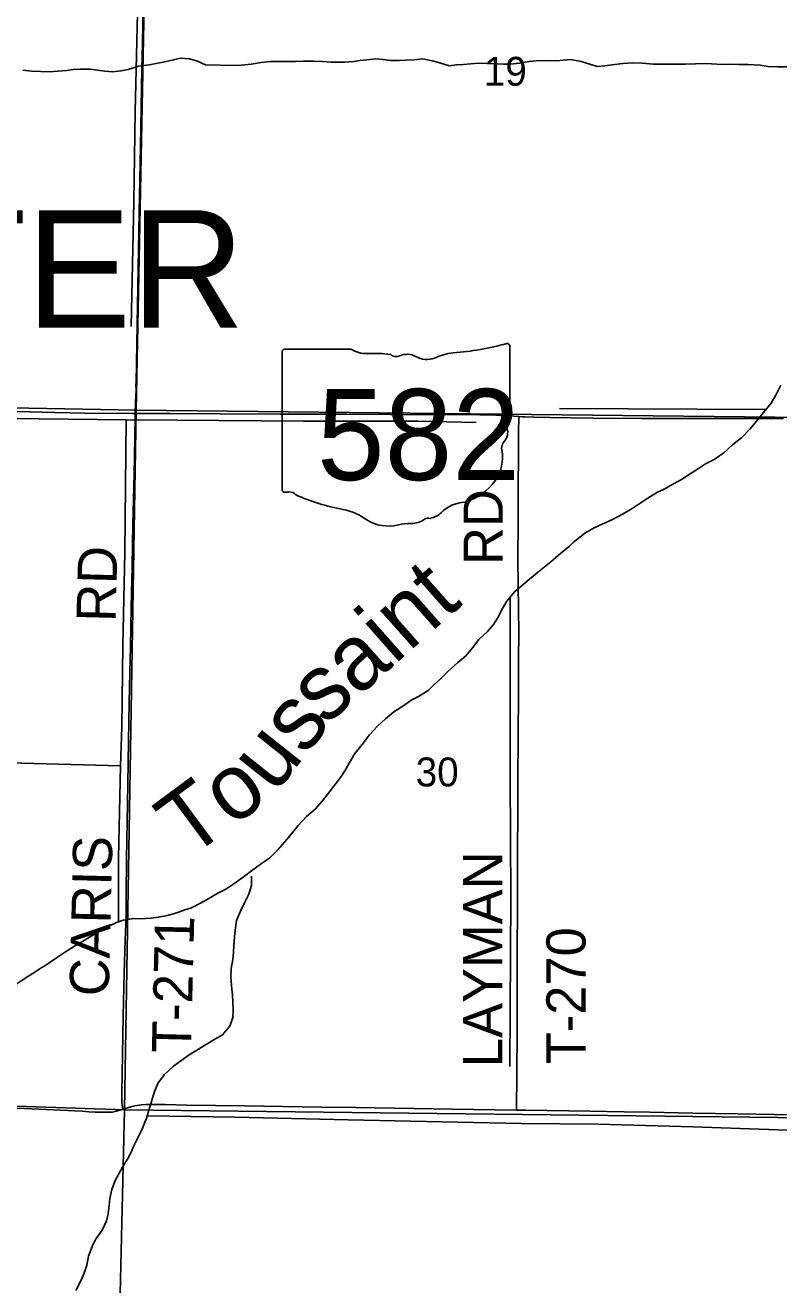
# Model space of a CAD drawing. Extents: x 1443599 to 1910620, y 1028088 to 1361369.
# Drawn here: x 1684560 to 1690325, y 1254320 to 1263955 of the extents above; entities that cross this region are included whole.
import ezdxf

# ---------------------------------------------------------------- set-up
doc = ezdxf.new("R2010")
doc.units = 0
for name, color, linetype in [('GM_X_Major_River', 7, 'Continuous'), ('GM_X_Major_River_Text', 7, 'Continuous'), ('GM_X_Minor_River', 7, 'Continuous'), ('GM_X_Section', 7, 'Continuous'), ('GM_X_Section_Text', 7, 'Continuous'), ('GM_X_State_Location', 7, 'Continuous'), ('GM_X_State_Route', 7, 'Continuous'), ('GM_X_State_Shield', 7, 'Continuous'), ('GM_X_Township_Road', 7, 'Continuous'), ('GM_X_Township_Road_Text', 7, 'Continuous'), ('GM_X_Township_Text', 7, 'Continuous')]:
    doc.layers.add(name, color=color, linetype=linetype)

msp = doc.modelspace()

# ---------------------------------------------------------------- linework, layer by layer
at = {"layer": 'GM_X_Major_River'}
for points in [[(1690341.6, 1261202.1), (1690306.2, 1261130.5), (1690266.9, 1261065), (1690209.5, 1260993.9), (1690156.2, 1260928.7), (1690102.9, 1260865.5), (1690041.6, 1260802.4), (1689970.4, 1260745.6), (1689905.1, 1260684.7), (1689832.1, 1260633.9), (1689765.3, 1260599), (1689702.4, 1260560.1), (1689633.5, 1260515.3), (1689585.9, 1260483.3), (1689518.9, 1260446.5), (1689449.6, 1260407.6), (1689397.7, 1260383.8), (1689324.2, 1260338.3), (1689248.5, 1260289.9), (1689195.7, 1260252.8), (1689128.9, 1260213.9), (1689054, 1260175.2), (1688975.2, 1260138.6), (1688912.5, 1260111.7), (1688842, 1260071), (1688751.2, 1259998.5), (1688723, 1259970.4), (1688640.9, 1259901.1), (1688581.1, 1259851.1), (1688503.8, 1259790.4), (1688432.5, 1259729.6), (1688369.4, 1259676.6), (1688302.2, 1259621.7), (1688244.8, 1259550.6), (1688207.5, 1259485.1), (1688180.5, 1259431.4)], [(1688180.5, 1259431.4), (1688143.3, 1259371.9), (1688096.2, 1259318.6), (1688030.9, 1259255.7), (1687981.6, 1259192.4), (1687930.4, 1259131.2), (1687869.3, 1259080.2), (1687793.9, 1259011.4), (1687732.6, 1258950.4), (1687681.7, 1258905.2), (1687641.9, 1258865.7), (1687567.9, 1258821.1), (1687517.3, 1258793.9), (1687448.3, 1258747.1), (1687381.4, 1258704.2), (1687316.2, 1258649.3), (1687255, 1258592.3), (1687193.7, 1258527.2), (1687138.2, 1258454.1), (1687082.8, 1258384.9), (1687039.4, 1258311.5), (1687010.4, 1258259.9), (1686977.3, 1258208.3), (1686940.3, 1258156.9), (1686835.6, 1258022.4), (1686778.3, 1257959.3), (1686713.1, 1257902.4), (1686647.7, 1257833.4), (1686598.4, 1257770.1), (1686545.2, 1257706.9), (1686489.9, 1257643.8), (1686428.7, 1257584.8), (1686367.7, 1257541.8), (1686300.7, 1257494.9), (1686227.5, 1257438.1), (1686156.4, 1257387.3), (1686095.6, 1257346.3), (1686028.8, 1257313.5), (1685966, 1257276.6), (1685901.2, 1257239.7), (1685832.4, 1257204.9), (1685782, 1257187.8), (1685719.5, 1257166.9), (1685647, 1257146.2), (1685580.6, 1257131.4), (1685522.8, 1257125.9), (1685444.1, 1257120), (1685388.7, 1257121.5), (1685309.6, 1257108.6), (1685259.2, 1257091.5), (1685190.5, 1257058.7), (1685060.8, 1256984.9), (1685010.2, 1256953.8), (1684937.2, 1256911), (1684868.3, 1256868.2), (1684807.4, 1256827.2), (1684709.6, 1256761.1), (1684675, 1256739.5), (1684625.2, 1256707), (1684568.1, 1256671.3), (1684495.5, 1256622.6)]]:
    msp.add_lwpolyline(points, dxfattribs=at)
at = {"layer": 'GM_X_Minor_River'}
for points in [[(1685371, 1261651.6), (1685390.1, 1262604.6), (1685401.7, 1263292.8), (1685422.4, 1264159.4), (1685430.6, 1265010.4), (1685453.1, 1266079.7), (1685460.4, 1266760.1), (1685484.5, 1267815.3), (1685493.9, 1268567.9)], [(1686505, 1263676.7), (1686438.9, 1263676.6), (1686366.5, 1263670.6), (1686288, 1263656.8), (1686215.6, 1263648.8), (1686165.4, 1263646.3), (1685939.1, 1263652.8), (1685877.8, 1263680.6), (1685816.2, 1263698.4), (1685746.1, 1263702.5), (1685683.6, 1263688.2), (1685615, 1263672.1), (1685560.6, 1263661.6), (1685510.2, 1263653), (1685427.7, 1263641.3), (1685346.8, 1263617.6), (1685292.4, 1263605.1), (1685228.1, 1263598.9), (1685170, 1263602.6), (1685112.2, 1263612.3), (1685060.2, 1263617.8), (1684984.1, 1263619.9), (1684927.9, 1263615.5), (1684875.6, 1263609), (1684809.3, 1263604.9), (1684747, 1263598.6), (1684680.9, 1263600.6), (1684610.9, 1263604.6), (1684542.9, 1263610.5)], [(1690402.3, 1263637.1), (1690316.1, 1263635.6), (1690244, 1263639.7), (1690182.2, 1263649.5), (1690092.1, 1263654.1), (1690020, 1263654.1), (1689949.9, 1263658.1), (1689893.7, 1263655.7), (1689811.7, 1263660.1), (1689755.6, 1263661.7), (1689689.4, 1263659.6), (1689611.2, 1263657.8), (1689555.1, 1263657.4), (1689500.9, 1263657), (1689432.8, 1263656.9), (1689366.6, 1263656.8), (1689280.7, 1263665.3), (1689208.6, 1263667.3), (1689132.3, 1263663.5), (1689051.8, 1263651.8), (1688995.5, 1263645.4), (1688935.2, 1263639.1), (1688879.6, 1263656.7), (1688814, 1263676.7), (1688734.3, 1263693), (1688678, 1263686.6), (1688625.8, 1263682.1), (1688497.6, 1263685.8), (1688413.2, 1263678.1), (1688344.7, 1263666.1), (1688270.3, 1263656.1), (1688220.2, 1263657.6), (1688170.1, 1263659), (1688110.1, 1263662.7), (1688030, 1263665), (1687965.7, 1263660.9), (1687913.4, 1263654.3), (1687859.2, 1263651.9), (1687804.9, 1263645.4), (1687731.4, 1263667.6), (1687673.7, 1263683.3), (1687602, 1263697.4), (1687535.7, 1263691.3), (1687471.4, 1263687.1), (1687421.2, 1263684.5), (1687357.1, 1263686.3), (1687299.2, 1263694), (1687241.2, 1263697.7), (1687172.9, 1263691.6), (1687122.6, 1263685.1), (1687072.2, 1263676.5), (1687006, 1263672.3), (1686949.9, 1263671.9), (1686899.8, 1263673.4), (1686835.7, 1263677.2), (1686763.7, 1263679.3), (1686687.5, 1263679.5), (1686629.3, 1263677.1), (1686561.2, 1263677.1), (1686505, 1263676.7)], [(1688009.8, 1260915.4), (1687561.1, 1260926.2), (1686689.2, 1260927.2), (1685721.4, 1260934.9), (1685332.6, 1260936), (1683777.7, 1260954.6), (1682361.3, 1260975.2), (1681407.5, 1260984.5), (1680213.9, 1261018.8), (1679332.8, 1261046.1), (1678157.2, 1261081.8), (1677840.8, 1261088.9)], [(1690228.1, 1261016.9), (1688648.2, 1261023.5)], [(1685332.6, 1260936), (1685323.7, 1259922.5), (1685307.5, 1259210.4), (1685299.7, 1258586.3), (1685289.2, 1258289.5), (1685275.1, 1257583.3), (1685275.3, 1257096.9)], [(1685289.2, 1258289.5), (1684534.2, 1258311.2), (1683939.7, 1258336.3), (1683224.6, 1258352.8), (1681998.9, 1258386), (1681270, 1258410.9), (1680665.3, 1258430.3), (1679916.1, 1258443.8), (1679291.2, 1258461.7), (1678948.9, 1258475.6), (1677961.6, 1258503.9), (1677304.9, 1258528.8), (1677312, 1258920), (1677321, 1259588.2), (1677326, 1259833)], [(1688269.4, 1259581.1), (1688271.1, 1258199.9), (1688275, 1257282.4), (1688268.2, 1255989.9)], [(1686291.4, 1257445.8), (1686291.4, 1257375.5), (1686271.4, 1257307.8), (1686239.6, 1257246.5), (1686207.6, 1257179.2), (1686177.5, 1257107.8), (1686165.4, 1257033.8), (1686161.9, 1256979.8), (1686156, 1256915.7), (1686154.5, 1256861.5), (1686148.9, 1256807.5), (1686137, 1256739.6), (1686133.2, 1256675.5), (1686139.3, 1256609.1), (1686145.2, 1256534.6), (1686147.8, 1256484.3), (1686152, 1256422), (1686148.4, 1256365.9), (1686126.4, 1256298.3), (1686068.5, 1256233.7), (1686003.2, 1256193.4), (1685927.7, 1256147.4), (1685864.5, 1256111.1), (1685813.5, 1256078.4), (1685750.1, 1256034.1), (1685694.8, 1255993.5), (1685626.9, 1255929.2), (1685577, 1255866.4), (1685549, 1255799), (1685529, 1255731.3), (1685509, 1255663.6), (1685489, 1255594), (1685456.8, 1255518.6), (1685424.8, 1255449.3), (1685393, 1255387.9), (1685371.4, 1255334.4), (1685341.8, 1255281), (1685308.2, 1255225.8), (1685276.5, 1255170.5), (1685249, 1255119.1), (1685223, 1255049.6), (1685209, 1254981.7), (1685203.5, 1254929.7), (1685195.6, 1254863.7), (1685182.1, 1254809.9), (1685148, 1254738.6), (1685097.8, 1254665.8), (1685072.3, 1254614.3), (1685044.1, 1254538.8), (1685032.1, 1254470.9), (1685012.3, 1254409.3), (1684988.7, 1254355.8), (1684948.4, 1254276.6)], [(1685494.2, 1255611.9), (1686166.7, 1255602.6), (1687032, 1255581.8), (1687869.3, 1255563.8), (1688354, 1255553.9), (1688943.2, 1255549), (1689668.1, 1255528.2), (1690320.9, 1255505.5), (1690749.5, 1255495.2), (1690911.7, 1255490.5), (1691374.7, 1255491.3), (1691877.8, 1255490.9), (1692328.8, 1255492), (1692879.8, 1255484.2), (1693138.1, 1255478.8)]]:
    msp.add_lwpolyline(points, dxfattribs=at)
at = {"layer": 'GM_X_Section'}
for points in [[(1685513.1, 1266304.8), (1685409, 1261011.2), (1680077.5, 1261109.8), (1680205.7, 1266419)], [(1685514.1, 1266390.8), (1691034.3, 1266328.1), (1690993.2, 1260949.6), (1685409, 1261011.2), (1685513.1, 1266304.8)], [(1685409, 1261011.2), (1685320.2, 1255659.5), (1679985.7, 1255840.2), (1680077.5, 1261109.8)], [(1685409, 1261011.2), (1690993.2, 1260949.6), (1690974.3, 1255593.1), (1685320.2, 1255659.5)], [(1685320.2, 1255659.5), (1685195.9, 1250354.2), (1679871.7, 1250556.9), (1679985.7, 1255840.2)], [(1685320.2, 1255659.5), (1690974.3, 1255593.1), (1690966.7, 1252219.4), (1690933.9, 1250280.8), (1690883.9, 1250279.4), (1685195.9, 1250354.2)]]:
    msp.add_lwpolyline(points, close=True, dxfattribs=at)
at = {"layer": 'GM_X_State_Route'}
msp.add_lwpolyline([(1684499.4, 1261000), (1684786.6, 1260992.6), (1685016.4, 1260988.4), (1685377.7, 1260985.4), (1685401.8, 1260985.4), (1685500.9, 1260985.6), (1685665, 1260985.2), (1686050.8, 1260982.2), (1686510.5, 1260981.2), (1687019.5, 1260979.5), (1687356.1, 1260977.5), (1688037.4, 1260974.3), (1688160.4, 1260971.8), (1688232.5, 1260968), (1688298.7, 1260965.6), (1688335.5, 1260962.7), (1688361.1, 1260960.1), (1688382, 1260958.4), (1688450.4, 1260957.2), (1688573.6, 1260954.2), (1688901.8, 1260950.3), (1689271.5, 1260948), (1689443.3, 1260946.9), (1689820.8, 1260945.8), (1690050.6, 1260946.6), (1690362.3, 1260947.5)], dxfattribs=at)
at = {"layer": 'GM_X_State_Shield'}
for p, q in [((1688266.6, 1260950.1), (1688266.6, 1261502.8)), ((1686526.4, 1261458.5), (1686526.4, 1260401.8)), ((1687053.2, 1261476.7), (1686543.6, 1261476.7)), ((1688266.5, 1260950.2), (1688266.6, 1260950.1))]:
    msp.add_line(p, q, dxfattribs=at)
for centre, major_axis, start_param, end_param in [((1687646.7, 1262917.2), (1845.5, 0), 4.814394, 5.042369), ((1688247.3, 1261505.1), (19.4, 0), 6.141152, 7.989035), ((1686546.4, 1261460.7), (20.2, 0), 1.712693, 3.28349), ((1687174.6, 1261599.3), (195.5, 0), 4.042523, 4.731795), ((1687239.4, 1260883.4), (702, 0), 1.404758, 1.657858), ((1687398.8, 1261466.2), (56.4, 0), 3.836095, 5.185415), ((1687481.6, 1261344.1), (117.3, 0), 0.950623, 2.079405), ((1687633, 1261511.6), (141.1, 0), 4.081561, 5.145723), ((1687882.1, 1261153.9), (371.3, 0), 1.699011, 2.107814), ((1688262.2, 1260909.5), (30, 0), 1.883978, 3.671073), ((1688246, 1260948), (20.7, 0), 5.05454, 6.418171), ((1688071.4, 1260839.7), (180, 0), 5.934695, 6.695948), ((1688336, 1260718.8), (130.9, 0), 2.387724, 3.262537), ((1687750.1, 1260648.5), (461.6, 0), 5.101752, 6.440018), ((1686546.6, 1260399.5), (20.3, 0), 3.00124, 4.508301), ((1686549.6, 1260507.6), (155.2, 0), 4.665946, 4.897461), ((1686581.4, 1260340.9), (56, 0), 0.519207, 1.627899), ((1687288, 1261290.2), (1332.7, 0), 4.195997, 4.488961), ((1686890.7, 1259927.1), (417, 0), 0.823519, 1.323587), ((1687944.8, 1260105.2), (252.8, 0), 1.647645, 2.488434), ((1687341.6, 1260335.6), (264.6, 0), 4.026481, 4.996735), ((1687494.5, 1259970.3), (217.4, 0), 1.495662, 1.94098), ((1687513.9, 1260256.5), (141, 0), 4.691044, 5.507374), ((1687641.4, 1260154.2), (39.7, 0), 1.147584, 2.315152), ((1687624.5, 1260299.4), (149.1, 0), 4.937069, 5.64225)]:
    msp.add_ellipse(centre, major_axis=major_axis, ratio=0.8, start_param=start_param, end_param=end_param, dxfattribs=at)
at = {"layer": 'GM_X_Township_Road'}
for points in [[(1685401.8, 1260985.4), (1685404.8, 1261070.8), (1685408.1, 1261169.2), (1685406.9, 1261202), (1685408.1, 1261226.6), (1685411.5, 1261366), (1685418, 1261669.6), (1685427.7, 1262235.9), (1685433.1, 1262523.1), (1685443.2, 1263023.7), (1685453.5, 1263622.8), (1685458.2, 1263811.5), (1685461.2, 1263959.2), (1685466.2, 1264221.8), (1685472.4, 1264426.9), (1685477, 1264607.4), (1685486.8, 1264984.9), (1685495.4, 1265313.1), (1685503.1, 1265567.4), (1685512.9, 1265928.4), (1685515.7, 1266051.5), (1685520.4, 1266256.7), (1685522, 1266338.6)], [(1685307, 1255663.2), (1685302.5, 1255696), (1685300.3, 1255712.3), (1685298.9, 1255736.9), (1685299, 1255786.1), (1685310.2, 1256377), (1685316.5, 1256705.2), (1685324.5, 1256959.6), (1685329.2, 1257082.6), (1685331.6, 1257164.6), (1685332.7, 1257304.1), (1685336.1, 1257575), (1685344.5, 1258149.5), (1685350.1, 1258477.7), (1685352.2, 1258625.4), (1685355.7, 1258773.1), (1685361.2, 1259002.9), (1685365.2, 1259199.8), (1685371.5, 1259503.5), (1685378.3, 1259815.3), (1685384.1, 1260135.3), (1685393.2, 1260521), (1685398.7, 1260800), (1685401.3, 1260972.3), (1685401.8, 1260985.4)], [(1688317.6, 1255657.4), (1688318, 1255685.2), (1688321.2, 1255906.8), (1688323.2, 1256284.4), (1688324.4, 1256522.5), (1688324.5, 1256883.7), (1688325.4, 1257195.6), (1688327.3, 1257614.2), (1688329.2, 1257959), (1688329.9, 1258131.4), (1688332.3, 1258558.2), (1688334.4, 1258804.5), (1688333.4, 1259009.7), (1688334.3, 1259116.4), (1688335.6, 1259297), (1688334.4, 1259502.2), (1688331.6, 1259666.3), (1688329.6, 1259879.8), (1688330.6, 1260158.9), (1688332, 1260429.8), (1688334.7, 1260659.6), (1688335.1, 1260864.8), (1688335.4, 1260937.6), (1688335.5, 1260962.7)], [(1680385.4, 1255805.9), (1680469.8, 1255804.1), (1680650.2, 1255799), (1681011.2, 1255791), (1681339.3, 1255782.5), (1681733.1, 1255774.3), (1682061.3, 1255766.3), (1682602.6, 1255749.8), (1682733.9, 1255745.6), (1683143.9, 1255728.8), (1683357.1, 1255719.9), (1683537.4, 1255711.8), (1683996.5, 1255691.2), (1684275.2, 1255679.6), (1684554, 1255668.3), (1684996.7, 1255647.4), (1685046.2, 1255643.8), (1685095.5, 1255641.7), (1685144.6, 1255641.5), (1685197.3, 1255640), (1685227.7, 1255641.7), (1685259.8, 1255648.7), (1685292.8, 1255659.1), (1685307, 1255663.2)], [(1685307, 1255663.2), (1685368.1, 1255681.2), (1685400.2, 1255689), (1685432.7, 1255695.3), (1685449.1, 1255697.5), (1685482.2, 1255700.1), (1685531.7, 1255700.4), (1685630.2, 1255698.6), (1685794.3, 1255694.8), (1686237.3, 1255688.6), (1686828.1, 1255679.6), (1687090.7, 1255675.7), (1687533.7, 1255669), (1687829.1, 1255664.8), (1688317.6, 1255657.4)], [(1688317.6, 1255657.4), (1688387.1, 1255656.3), (1688879.4, 1255649.1), (1689141.9, 1255643.5), (1689338.9, 1255640.7), (1689667.1, 1255634), (1690011.7, 1255628.4), (1690290.6, 1255623.6), (1690487.6, 1255620.5), (1690635.2, 1255617.5), (1690864.8, 1255614.9), (1690984.8, 1255613.5)]]:
    msp.add_lwpolyline(points, dxfattribs=at)

# ---------------------------------------------------------------- texts
at = {"layer": 'GM_X_Major_River_Text'}
for s, rotation, p in [('saint', 41.51124, (1686855.6, 1258591.6)), ('us', 51.51074, (1686469.4, 1258070)), ('To', 36.51067, (1685812.3, 1257572.8))]:
    msp.add_text(s, height=500.3, rotation=rotation, dxfattribs=at).set_placement(p)
at = {"layer": 'GM_X_Section_Text'}
for s, p in [('19', (1688069, 1263492)), ('30', (1687547.6, 1258132.8))]:
    msp.add_text(s, height=221, rotation=0.00001, dxfattribs=at).set_placement(p)
at = {"layer": 'GM_X_State_Location'}
for s in ['s', 'r']:
    msp.add_text(s, height=1, dxfattribs=at).set_placement((1687377, 1260859.9))
msp.add_text('582', height=1, rotation=0.00001, dxfattribs=at).set_placement((1687024, 1260787.2))
at = {"layer": 'GM_X_State_Shield'}
msp.add_text('582', height=696.1, dxfattribs=at).set_placement((1686792.2, 1260476.3))
at = {"layer": 'GM_X_Township_Road_Text'}
for s, rotation, p in [('RD', 90, (1688213.9, 1259826.5)), ('RD', 88.5113, (1685251.6, 1259388.5)), ('CARIS', 88.61343, (1685198.8, 1256524.8)), ('LAYMAN', 90, (1688209.4, 1255985.3)), ('T-271', 88.61378, (1685828.6, 1256091.3)), ('T-270', 90, (1688847.1, 1256007.3))]:
    msp.add_text(s, height=300, rotation=rotation, dxfattribs=at).set_placement(p)
at = {"layer": 'GM_X_Township_Text'}
msp.add_text('WEBSTER', height=900, rotation=0.00001, dxfattribs=at).set_placement((1680289, 1261640.4))

doc.saveas('drawing.dxf')
